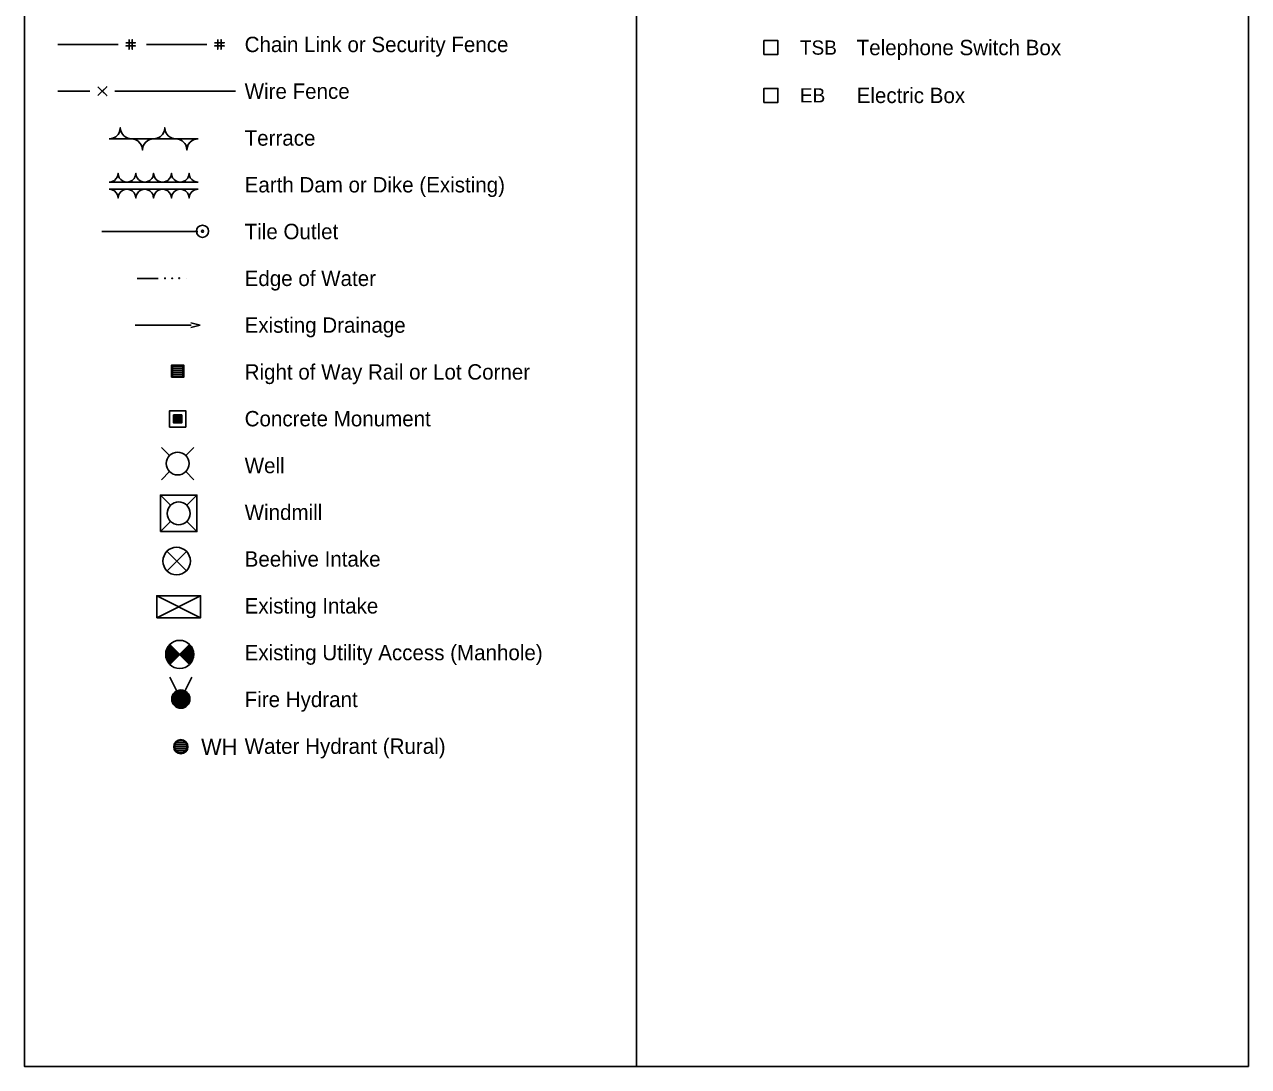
# Model space of a CAD drawing. Extents: x 6082259 to 6083454, y 5964102 to 5966092.
# Drawn here: x 6082259 to 6083454, y 5964102 to 5965119 of the extents above; entities that cross this region are included whole.
import ezdxf

# ---------------------------------------------------------------- set-up
doc = ezdxf.new("R2010")
doc.units = 0
for name, color, linetype in [('Default', 7, 'Continuous'), ('dsnCellElements', 7, 'Continuous'), ('SheetBorder', 7, 'Continuous')]:
    doc.layers.add(name, color=color, linetype=linetype)

msp = doc.modelspace()

# ---------------------------------------------------------------- linework, layer by layer
at = {"layer": 'Default'}
for points in [[(6082259, 5966092.2), (6082856.5, 5966092.2), (6082856.5, 5964102.2), (6082259, 5964102.2)], [(6082856.5, 5966092.2), (6083454, 5966092.2), (6083454, 5964102.2), (6082856.5, 5964102.2)]]:
    msp.add_lwpolyline(points, close=True, dxfattribs=at)
at = {"layer": 'dsnCellElements'}
for p, q in [((6082334.7, 5964916.8), (6082428.3, 5964916.8)), ((6082369, 5964871.1), (6082389.5, 5964871.1)), ((6082410, 5964871.1), (6082410, 5964871.1)), ((6082417, 5964871.3), (6082417, 5964871.3)), ((6082367, 5964825.4), (6082421.8, 5964825.4)), ((6082421.5, 5964827.8), (6082430.6, 5964825.5)), ((6082430.6, 5964825.5), (6082421.5, 5964823.2)), ((6082392.8, 5964706.1), (6082400.7, 5964698.3)), ((6082416.5, 5964698.3), (6082424.4, 5964706.1)), ((6082392.8, 5964674.6), (6082400.7, 5964682.5)), ((6082416.5, 5964682.5), (6082424.4, 5964674.6)), ((6082391.8, 5964659.7), (6082401.7, 5964649.7)), ((6082417.5, 5964649.7), (6082427.4, 5964659.7)), ((6082391.8, 5964624), (6082401.7, 5964634)), ((6082417.5, 5964634), (6082427.4, 5964624)), ((6082398.2, 5964585.8), (6082417.1, 5964604.7)), ((6082398.2, 5964604.7), (6082417.1, 5964585.8)), ((6082400.9, 5964494.5), (6082420.3, 5964513.9)), ((6082400.9, 5964513.9), (6082420.3, 5964494.5)), ((6082401, 5964482), (6082411.7, 5964460.6)), ((6082411.7, 5964460.6), (6082422.4, 5964482))]:
    msp.add_line(p, q, dxfattribs=at)
for points in [[(6082291.6, 5965099.3), (6082350.5, 5965099.3)], [(6082361.1, 5965104), (6082361.1, 5965094.6), (6082361.1, 5965097.8), (6082358, 5965097.8), (6082367.3, 5965097.8), (6082364.2, 5965097.8), (6082364.2, 5965094.6), (6082364.2, 5965104), (6082364.2, 5965100.9), (6082367.3, 5965100.9), (6082358, 5965100.9)], [(6082378.3, 5965099.3), (6082437.2, 5965099.3)], [(6082447.8, 5965104), (6082447.8, 5965094.6), (6082447.8, 5965097.8), (6082444.7, 5965097.8), (6082454, 5965097.8), (6082450.9, 5965097.8), (6082450.9, 5965094.6), (6082450.9, 5965104), (6082450.9, 5965100.9), (6082454, 5965100.9), (6082444.7, 5965100.9)], [(6082987.8, 5965089.5), (6082987.8, 5965089.5), (6082994.6, 5965089.5), (6082994.6, 5965103.1), (6082981, 5965103.1), (6082981, 5965089.5), (6082987.8, 5965089.5)], [(6082330.6, 5965049.4), (6082339.3, 5965058), (6082334.9, 5965053.7), (6082339.3, 5965049.4), (6082330.6, 5965058)], [(6082291.6, 5965053.7), (6082322.8, 5965053.7)], [(6082347.1, 5965053.7), (6082464.9, 5965053.7)], [(6082987.8, 5965042.8), (6082987.8, 5965042.8), (6082994.6, 5965042.8), (6082994.6, 5965056.4), (6082981, 5965056.4), (6082981, 5965042.8), (6082987.8, 5965042.8)], [(6082341.8, 5965007.1), (6082345.4, 5965007.7), (6082348.1, 5965009.2), (6082350.5, 5965011.5), (6082351.5, 5965013.1), (6082352.2, 5965015.2), (6082352.6, 5965018), (6082353, 5965014.9), (6082354, 5965012.6), (6082355.9, 5965010.2), (6082357.9, 5965008.7), (6082359.8, 5965007.8), (6082363.4, 5965007.1)], [(6082385.1, 5965007.1), (6082388.7, 5965007.7), (6082391.5, 5965009.2), (6082393.8, 5965011.5), (6082394.8, 5965013.1), (6082395.6, 5965015.2), (6082396, 5965018), (6082396.4, 5965014.9), (6082397.4, 5965012.6), (6082399.2, 5965010.2), (6082401.2, 5965008.7), (6082403.2, 5965007.8), (6082406.8, 5965007.1)], [(6082341.8, 5965007.1), (6082428.5, 5965007.1)], [(6082363.4, 5965007.1), (6082367, 5965006.5), (6082369.8, 5965005.1), (6082372.1, 5965002.8), (6082373.1, 5965001.2), (6082373.9, 5964999.1), (6082374.3, 5964996.3), (6082374.7, 5964999.3), (6082375.7, 5965001.7), (6082377.5, 5965004), (6082379.6, 5965005.6), (6082381.5, 5965006.5), (6082385.1, 5965007.1)], [(6082406.8, 5965007.1), (6082410.4, 5965006.5), (6082413.1, 5965005.1), (6082415.5, 5965002.8), (6082416.5, 5965001.2), (6082417.3, 5964999.1), (6082417.6, 5964996.3), (6082418.1, 5964999.3), (6082419, 5965001.7), (6082420.9, 5965004), (6082422.9, 5965005.6), (6082424.8, 5965006.5), (6082428.5, 5965007.1)], [(6082341.8, 5964965), (6082344.6, 5964965.5), (6082346.8, 5964966.6), (6082348.7, 5964968.4), (6082349.5, 5964969.7), (6082350.2, 5964971.4), (6082350.4, 5964973.6), (6082350.8, 5964971.2), (6082351.6, 5964969.3), (6082353, 5964967.4), (6082354.7, 5964966.2), (6082356.2, 5964965.5), (6082359.1, 5964965)], [(6082341.8, 5964965), (6082428.5, 5964965)], [(6082359.1, 5964965), (6082362, 5964965.5), (6082364.2, 5964966.6), (6082366.1, 5964968.4), (6082366.9, 5964969.7), (6082367.5, 5964971.4), (6082367.8, 5964973.6), (6082368.1, 5964971.2), (6082368.9, 5964969.3), (6082370.4, 5964967.4), (6082372, 5964966.2), (6082373.5, 5964965.5), (6082376.5, 5964965)], [(6082376.5, 5964965), (6082379.3, 5964965.5), (6082381.5, 5964966.6), (6082383.4, 5964968.4), (6082384.2, 5964969.7), (6082384.8, 5964971.4), (6082385.1, 5964973.6), (6082385.5, 5964971.2), (6082386.3, 5964969.3), (6082387.7, 5964967.4), (6082389.3, 5964966.2), (6082390.9, 5964965.5), (6082393.8, 5964965)], [(6082393.8, 5964965), (6082396.6, 5964965.5), (6082398.9, 5964966.6), (6082400.7, 5964968.4), (6082401.5, 5964969.7), (6082402.2, 5964971.4), (6082402.5, 5964973.6), (6082402.8, 5964971.2), (6082403.6, 5964969.3), (6082405.1, 5964967.4), (6082406.7, 5964966.2), (6082408.2, 5964965.5), (6082411.1, 5964965)], [(6082411.1, 5964965), (6082414, 5964965.5), (6082416.2, 5964966.6), (6082418.1, 5964968.4), (6082418.9, 5964969.7), (6082419.5, 5964971.4), (6082419.8, 5964973.6), (6082420.1, 5964971.2), (6082420.9, 5964969.3), (6082422.4, 5964967.4), (6082424, 5964966.2), (6082425.5, 5964965.5), (6082428.5, 5964965)], [(6082341.8, 5964958), (6082359.1, 5964958)], [(6082341.8, 5964958), (6082344.6, 5964957.5), (6082346.8, 5964956.4), (6082348.7, 5964954.6), (6082349.5, 5964953.3), (6082350.2, 5964951.6), (6082350.4, 5964949.4), (6082350.8, 5964951.8), (6082351.6, 5964953.7), (6082353, 5964955.6), (6082354.7, 5964956.8), (6082356.2, 5964957.5), (6082359.1, 5964958)], [(6082359.1, 5964958), (6082376.4, 5964958)], [(6082359.1, 5964958), (6082362, 5964957.5), (6082364.2, 5964956.4), (6082366.1, 5964954.6), (6082366.9, 5964953.3), (6082367.5, 5964951.6), (6082367.8, 5964949.4), (6082368.1, 5964951.8), (6082368.9, 5964953.7), (6082370.4, 5964955.6), (6082372, 5964956.8), (6082373.5, 5964957.5), (6082376.4, 5964958)], [(6082376.5, 5964958), (6082393.8, 5964958)], [(6082376.5, 5964958), (6082379.3, 5964957.5), (6082381.5, 5964956.4), (6082383.4, 5964954.6), (6082384.2, 5964953.3), (6082384.8, 5964951.6), (6082385.1, 5964949.4), (6082385.5, 5964951.8), (6082386.3, 5964953.7), (6082387.7, 5964955.6), (6082389.3, 5964956.8), (6082390.9, 5964957.5), (6082393.8, 5964958)], [(6082393.8, 5964958), (6082411.1, 5964958)], [(6082393.8, 5964958), (6082396.6, 5964957.5), (6082398.9, 5964956.4), (6082400.7, 5964954.6), (6082401.5, 5964953.3), (6082402.2, 5964951.6), (6082402.5, 5964949.4), (6082402.8, 5964951.8), (6082403.6, 5964953.7), (6082405.1, 5964955.6), (6082406.7, 5964956.8), (6082408.2, 5964957.5), (6082411.1, 5964958)], [(6082411.1, 5964958), (6082428.5, 5964958)], [(6082411.1, 5964958), (6082414, 5964957.5), (6082416.2, 5964956.4), (6082418.1, 5964954.6), (6082418.9, 5964953.3), (6082419.5, 5964951.6), (6082419.8, 5964949.4), (6082420.1, 5964951.8), (6082420.9, 5964953.7), (6082422.4, 5964955.6), (6082424, 5964956.8), (6082425.5, 5964957.5), (6082428.5, 5964958)], [(6082403.7, 5964775.6), (6082403.7, 5964785.5), (6082413.6, 5964785.5), (6082413.6, 5964775.6), (6082403.7, 5964775.6), (6082403.7, 5964777.5), (6082413.6, 5964777.5), (6082413.6, 5964779.5), (6082403.7, 5964779.5), (6082403.7, 5964781.5), (6082413.6, 5964781.5), (6082413.6, 5964783.5), (6082403.7, 5964783.5)], [(6082400.7, 5964726), (6082400.7, 5964741.9), (6082416.5, 5964741.9), (6082416.5, 5964726), (6082400.7, 5964726)], [(6082404.6, 5964730), (6082404.6, 5964737.9), (6082412.6, 5964737.9), (6082412.6, 5964730), (6082404.6, 5964730), (6082405.6, 5964731), (6082405.6, 5964736.9), (6082411.6, 5964736.9), (6082411.6, 5964731), (6082406.6, 5964731), (6082406.6, 5964735.9), (6082410.6, 5964735.9), (6082410.6, 5964732), (6082407.6, 5964732), (6082407.6, 5964734.9), (6082409.6, 5964734.9), (6082409.6, 5964733), (6082408.6, 5964733), (6082408.6, 5964734)], [(6082388.2, 5964540), (6082431, 5964561.4), (6082431, 5964540), (6082388.2, 5964561.4)], [(6082400.7, 5964495.3), (6082401.2, 5964495.3), (6082402.2, 5964496.3), (6082400.2, 5964496.3), (6082399.2, 5964497.3), (6082403.2, 5964497.3), (6082404.2, 5964498.3), (6082398.7, 5964498.3), (6082398.2, 5964499.3), (6082405.1, 5964499.3), (6082406.1, 5964500.3), (6082398.2, 5964500.3), (6082397.7, 5964501.2), (6082407.1, 5964501.2), (6082408.1, 5964502.2), (6082397.7, 5964502.2), (6082397.2, 5964503.2), (6082409.1, 5964503.2), (6082410.1, 5964504.2), (6082397.2, 5964504.2), (6082397.2, 5964505.2), (6082409.1, 5964505.2), (6082408.1, 5964506.2), (6082397.7, 5964506.2), (6082397.7, 5964507.2), (6082407.1, 5964507.2), (6082406.1, 5964508.2), (6082397.7, 5964508.2), (6082398.2, 5964509.2), (6082405.1, 5964509.2), (6082404.2, 5964510.2), (6082398.7, 5964510.2), (6082399.2, 5964511.1), (6082403.2, 5964511.1), (6082402.2, 5964512.1), (6082399.7, 5964512.1), (6082400.7, 5964513.1), (6082401.2, 5964513.1), (6082410.1, 5964504.2), (6082401.2, 5964495.3), (6082400.7, 5964495.3), (6082399.2, 5964497.3), (6082397.7, 5964501.2), (6082397.2, 5964505.2), (6082398.2, 5964509.2), (6082400.7, 5964513.1)], [(6082420.5, 5964495.3), (6082420, 5964495.3), (6082419, 5964496.3), (6082421, 5964496.3), (6082422, 5964497.3), (6082418, 5964497.3), (6082417, 5964498.3), (6082422.5, 5964498.3), (6082423, 5964499.3), (6082416, 5964499.3), (6082415, 5964500.3), (6082423, 5964500.3), (6082423.5, 5964501.2), (6082414.1, 5964501.2), (6082413.1, 5964502.2), (6082423.5, 5964502.2), (6082424, 5964503.2), (6082412.1, 5964503.2), (6082411.1, 5964504.2), (6082424, 5964504.2), (6082424, 5964505.2), (6082412.1, 5964505.2), (6082413.1, 5964506.2), (6082423.5, 5964506.2), (6082423.5, 5964507.2), (6082414.1, 5964507.2), (6082415, 5964508.2), (6082423.5, 5964508.2), (6082423, 5964509.2), (6082416, 5964509.2), (6082417, 5964510.2), (6082422.5, 5964510.2), (6082422, 5964511.1), (6082418, 5964511.1), (6082419, 5964512.1), (6082421.5, 5964512.1), (6082420.5, 5964513.1), (6082420, 5964513.1), (6082411.1, 5964504.2), (6082420, 5964495.3), (6082420.5, 5964495.3), (6082422, 5964497.3), (6082423.5, 5964501.2), (6082424, 5964505.2), (6082423, 5964509.2), (6082420.5, 5964513.1)], [(6082413.2, 5964469), (6082410.2, 5964469), (6082406.3, 5964467.1), (6082404.3, 5964464.6), (6082403.3, 5964461.1), (6082403.8, 5964457.7), (6082406.3, 5964454.2), (6082408.7, 5964452.7), (6082411.7, 5964452.2), (6082414.7, 5964452.7), (6082417.7, 5964454.7), (6082419.6, 5964457.7), (6082420.1, 5964460.6), (6082419.6, 5964463.6), (6082418.2, 5964466.1), (6082415.7, 5964468.1), (6082413.2, 5964469), (6082416.7, 5964467.6), (6082407.3, 5964467.6), (6082405.3, 5964466.1), (6082418.2, 5964466.1), (6082419.1, 5964464.6), (6082404.3, 5964464.6), (6082403.8, 5964463.1), (6082419.6, 5964463.1), (6082420.1, 5964461.6), (6082403.3, 5964461.6), (6082403.3, 5964460.1), (6082420.1, 5964460.1), (6082419.6, 5964458.6), (6082403.8, 5964458.6), (6082404.3, 5964457.2), (6082419.1, 5964457.2), (6082418.2, 5964455.7), (6082405.3, 5964455.7), (6082406.3, 5964454.2), (6082417.2, 5964454.2), (6082414.7, 5964452.7), (6082408.7, 5964452.7)], [(6082413.7, 5964420), (6082409.7, 5964420), (6082406.8, 5964418), (6082405.8, 5964416), (6082405.8, 5964412.1), (6082406.8, 5964410.1), (6082409.7, 5964408.1), (6082413.7, 5964408.1), (6082416.7, 5964410.1), (6082417.7, 5964412.1), (6082417.7, 5964416), (6082416.7, 5964418), (6082413.7, 5964420), (6082416.7, 5964418), (6082406.8, 5964418), (6082405.8, 5964416), (6082417.7, 5964416), (6082417.7, 5964414.1), (6082405.8, 5964414.1), (6082405.8, 5964412.1), (6082417.7, 5964412.1), (6082416.7, 5964410.1), (6082406.8, 5964410.1)]]:
    msp.add_lwpolyline(points, dxfattribs=at)
for points in [[(6082402.7, 5964774.6), (6082402.7, 5964786.5), (6082414.6, 5964786.5), (6082414.6, 5964774.6)], [(6082391.8, 5964624), (6082391.8, 5964659.7), (6082427.4, 5964659.7), (6082427.4, 5964624)], [(6082388.2, 5964540), (6082388.2, 5964561.4), (6082431, 5964561.4), (6082431, 5964540)]]:
    msp.add_lwpolyline(points, close=True, dxfattribs=at)
for centre, radius in [((6082432.9, 5964917), 5.94), ((6082432.9, 5964917), 0.991), ((6082396.3, 5964871.1), 0.342), ((6082403.2, 5964871.1), 0.342), ((6082410, 5964871.3), 0.342), ((6082408.6, 5964690.4), 11.1), ((6082409.6, 5964641.8), 11.1), ((6082407.6, 5964595.3), 13.4), ((6082410.6, 5964504.2), 13.7), ((6082411.7, 5964460.6), 8.92), ((6082411.7, 5964414.1), 6.93)]:
    msp.add_circle(centre, radius, dxfattribs=at)

# ---------------------------------------------------------------- texts
for s, height, p in [('TSB', 13.87, (6083016.1, 5965089.3)), ('EB', 13.87, (6083016.1, 5965042.7)), ('Well', 15, (6082474, 5964681)), ('WH', 15.85, (6082431.5, 5964406.1))]:
    msp.add_text(s, height=height, dxfattribs=at).set_placement(p)
at = {"layer": 'SheetBorder'}
for s, p in [('Chain Link or Security Fence', (6082474, 5965091.8)), ('Telephone Switch Box', (6083071.5, 5965088.8)), ('Wire Fence', (6082474, 5965046.2)), ('Electric Box', (6083071.5, 5965042.1)), ('Terrace', (6082474, 5965000.5)), ('Earth Dam or Dike (Existing)', (6082474, 5964954.9)), ('Tile Outlet', (6082474, 5964909.3)), ('Edge of Water', (6082474, 5964863.6)), ('Existing Drainage', (6082474, 5964818)), ('Right of Way Rail or Lot Corner', (6082474, 5964772.3)), ('Concrete Monument', (6082474, 5964726.7)), ('Windmill', (6082474, 5964635.4)), ('Beehive Intake', (6082474, 5964589.8)), ('Existing Intake', (6082474, 5964544.1)), ('Existing Utility Access (Manhole)', (6082474, 5964498.5)), ('Fire Hydrant', (6082474, 5964452.8)), ('Water Hydrant (Rural)', (6082474, 5964407.2))]:
    msp.add_text(s, height=15, dxfattribs=at).set_placement(p)

doc.saveas('drawing.dxf')
